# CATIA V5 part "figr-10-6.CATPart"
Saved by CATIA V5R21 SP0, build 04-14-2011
Part number: Part1
Bounding box of the stored display mesh (mm): x -9.616 to 10, y -9.533 to 9.835, z 0 to 10
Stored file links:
  D:\CATIA V5R21 E-RESOURCES\CATIA-V5R21\catia-v5r21-prt\c10-catia-v5r20-prt\c10-catia-v5r21-figr-10-6.CATPart
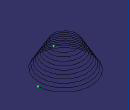
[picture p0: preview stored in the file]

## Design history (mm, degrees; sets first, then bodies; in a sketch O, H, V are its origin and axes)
Set1
  Helix1: Direction {line stored without definition}, RefPoint {point type Coord, X 10, Y 0, Z 0}, Pitch 1, Height 10, TaperAngle 30
Body1 (main body)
